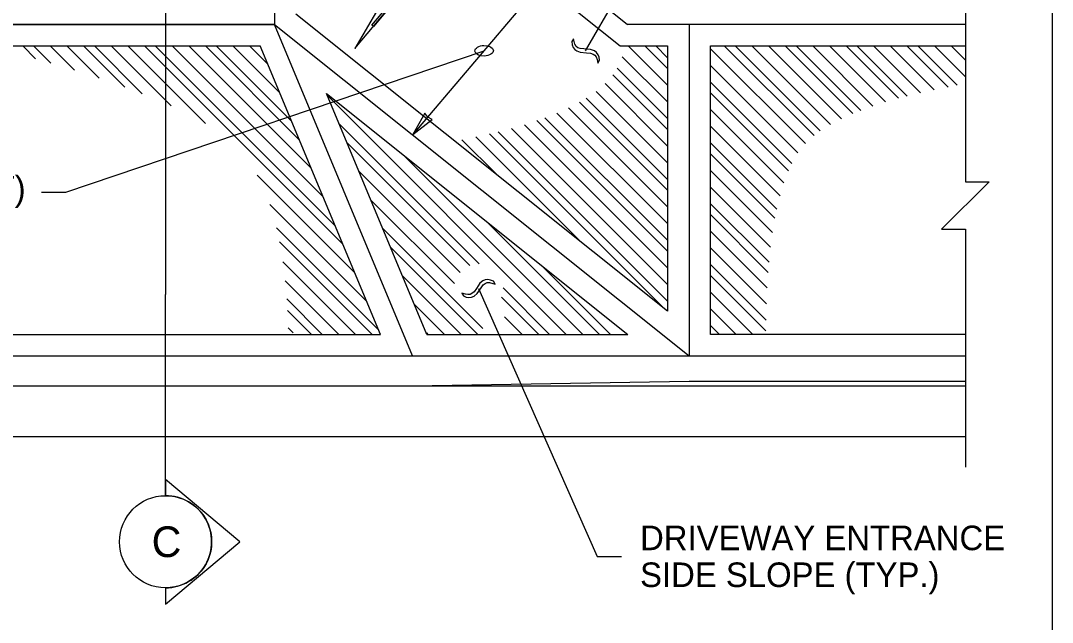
# Model space of a CAD drawing. Extents: x 99862 to 103151, y 100000 to 105076.
# Drawn here: x 102479 to 103151, y 101333 to 101725 of the extents above; entities that cross this region are included whole.
import ezdxf

# ---------------------------------------------------------------- set-up
doc = ezdxf.new("R2010")
doc.units = 0
for name, color, linetype in [('Level 1', 7, 'Continuous'), ('Level 15', 7, 'Continuous'), ('Level 20', 7, 'Continuous'), ('Level 48', 7, 'Continuous'), ('Level 50', 7, 'Continuous'), ('Level 57', 7, 'Continuous'), ('Level 58', 7, 'Continuous'), ('Level 9', 7, 'Continuous')]:
    doc.layers.add(name, color=color, linetype=linetype)

msp = doc.modelspace()

# ---------------------------------------------------------------- linework, layer by layer
at = {"layer": 'Level 1'}
msp.add_lwpolyline([(99862, 99999.5), (103151, 99999.5), (103151, 102075.5), (99862, 102075.5)], close=True, dxfattribs=at)
at = {"layer": 'Level 15'}
for p, q in [((102846.98, 101705.23), (102946.71, 101877.97)), ((102846.98, 101705.23), (102946.71, 101877.97)), ((102734.45, 101650.65), (102827.46, 101760.04)), ((102734.45, 101650.65), (102827.46, 101760.04)), ((102508.56, 101613.12), (102780.95, 101705.35)), ((102492.56, 101613.12), (102508.56, 101613.12)), ((102777.26, 101550.41), (102854.48, 101375.91)), ((102777.26, 101550.41), (102854.48, 101375.91)), ((102854.48, 101375.91), (102870.48, 101375.91)), ((102854.48, 101375.91), (102870.48, 101375.91))]:
    msp.add_line(p, q, dxfattribs=at)
for points in [[(103094.35, 101742.53), (103094.35, 101620.01), (103096.44, 101620.01)], [(103094.35, 101742.53), (103094.35, 101620.01), (103096.44, 101620.01)], [(103096.44, 101620.01), (103109.84, 101620.01), (103078.87, 101589.04), (103094.35, 101589.04), (103094.35, 101434.03)], [(103096.44, 101620.01), (103109.84, 101620.01), (103078.87, 101589.04), (103094.35, 101589.04), (103094.35, 101434.03)]]:
    msp.add_lwpolyline(points, dxfattribs=at)
msp.add_lwpolyline([(102734.45, 101650.66), (102746.98, 101660.64), (102744.16, 101662.08), (102742.28, 101664.63)], close=True, dxfattribs=at)
msp.add_lwpolyline([(102734.45, 101650.66), (102746.98, 101660.64), (102744.16, 101662.08), (102742.28, 101664.63)], close=True, dxfattribs=at)
msp.add_ellipse((102780.95, 101705.35), major_axis=(-6, -0.22), ratio=0.57735, dxfattribs=at)
at = {"layer": 'Level 20'}
for p, q in [((102573.44, 101794.07), (102573.44, 101717.31)), ((102573.44, 101717.31), (102573.44, 101546.41)), ((102573.44, 101717.31), (102573.44, 101546.41)), ((102839.03, 101713.11), (102837.97, 101711.28)), ((102839.03, 101713.11), (102837.97, 101711.28)), ((102837.97, 101711.28), (102838.33, 101709.17)), ((102837.97, 101711.28), (102838.33, 101709.17)), ((102838.33, 101709.17), (102838.98, 101707.51)), ((102838.33, 101709.17), (102838.98, 101707.51)), ((102838.98, 101707.51), (102839.93, 101706.21)), ((102838.98, 101707.51), (102839.93, 101706.21)), ((102840.01, 101709.55), (102839.03, 101713.12)), ((102840.01, 101709.55), (102839.03, 101713.12)), ((102840.88, 101708.16), (102840.01, 101709.55)), ((102840.88, 101708.16), (102840.01, 101709.55)), ((102841.97, 101707.24), (102840.88, 101708.16)), ((102841.97, 101707.24), (102840.88, 101708.16)), ((102843.37, 101706.71), (102841.97, 101707.24)), ((102843.37, 101706.71), (102841.97, 101707.24)), ((102839.93, 101706.21), (102841.26, 101705.2)), ((102839.93, 101706.21), (102841.26, 101705.2)), ((102841.26, 101705.2), (102843.56, 101704.31)), ((102841.26, 101705.2), (102843.56, 101704.31)), ((102845.79, 101706.5), (102843.37, 101706.71)), ((102845.79, 101706.5), (102843.37, 101706.71)), ((102843.56, 101704.31), (102847.64, 101704.05)), ((102843.56, 101704.31), (102847.64, 101704.05)), ((102850.18, 101706.13), (102845.79, 101706.5)), ((102850.18, 101706.13), (102845.79, 101706.5)), ((102847.64, 101704.05), (102850.18, 101703.82)), ((102847.64, 101704.05), (102850.18, 101703.82)), ((102852.74, 101705.2), (102850.18, 101706.13)), ((102852.74, 101705.2), (102850.18, 101706.13)), ((102850.18, 101703.82), (102851.99, 101703.19)), ((102850.18, 101703.82), (102851.99, 101703.19)), ((102851.99, 101703.19), (102853.04, 101702.37)), ((102851.99, 101703.19), (102853.04, 101702.37)), ((102854.14, 101704.13), (102852.74, 101705.2)), ((102854.14, 101704.13), (102852.74, 101705.2)), ((102853.04, 101702.37), (102853.85, 101701.27)), ((102853.04, 101702.37), (102853.85, 101701.27)), ((102853.85, 101701.27), (102854.47, 101699.65)), ((102853.85, 101701.27), (102854.47, 101699.65)), ((102855.15, 101702.76), (102854.14, 101704.13)), ((102855.15, 101702.76), (102854.14, 101704.13)), ((102855.79, 101701.08), (102855.15, 101702.76)), ((102855.79, 101701.08), (102855.15, 101702.76)), ((102856.04, 101699.11), (102855.79, 101701.08)), ((102856.04, 101699.11), (102855.79, 101701.08)), ((102854.47, 101699.65), (102854.99, 101697.28)), ((102854.47, 101699.65), (102854.99, 101697.28)), ((102854.99, 101697.28), (102856.04, 101699.11)), ((102854.99, 101697.28), (102856.04, 101699.11)), ((102778.17, 101553.83), (102775.9, 101550.43)), ((102778.17, 101553.83), (102775.9, 101550.43)), ((102780.09, 101555.38), (102778.17, 101553.83)), ((102780.09, 101555.38), (102778.17, 101553.83)), ((102778.95, 101550.81), (102780.34, 101552.8)), ((102778.95, 101550.81), (102780.34, 101552.8)), ((102781.63, 101556.02), (102780.09, 101555.38)), ((102781.63, 101556.02), (102780.09, 101555.38)), ((102780.34, 101552.8), (102781.5, 101553.75)), ((102780.34, 101552.8), (102781.5, 101553.75)), ((102781.5, 101553.75), (102782.84, 101554.23)), ((102781.5, 101553.75), (102782.84, 101554.23)), ((102783.23, 101556.2), (102781.63, 101556.02)), ((102783.23, 101556.2), (102781.63, 101556.02)), ((102782.84, 101554.23), (102784.48, 101554.28)), ((102782.84, 101554.23), (102784.48, 101554.28)), ((102784.99, 101555.93), (102783.23, 101556.2)), ((102784.99, 101555.93), (102783.23, 101556.2)), ((102784.48, 101554.28), (102788.06, 101553.35)), ((102784.48, 101554.28), (102788.06, 101553.35)), ((102787, 101555.18), (102784.99, 101555.93)), ((102787, 101555.18), (102784.99, 101555.93)), ((102788.06, 101553.35), (102787, 101555.19)), ((102788.06, 101553.35), (102787, 101555.19)), ((102573.44, 101442.03), (102573.44, 101546.41)), ((102768.68, 101546.71), (102766.37, 101547.45)), ((102766.37, 101547.45), (102767.42, 101545.62)), ((102768.68, 101546.71), (102766.37, 101547.45)), ((102766.37, 101547.45), (102767.42, 101545.62)), ((102770.39, 101546.44), (102768.68, 101546.71)), ((102770.39, 101546.44), (102768.68, 101546.71)), ((102771.74, 101546.59), (102770.39, 101546.44)), ((102771.74, 101546.59), (102770.39, 101546.44)), ((102772.98, 101547.09), (102771.74, 101546.59)), ((102772.98, 101547.09), (102771.74, 101546.59)), ((102774.43, 101548.34), (102772.98, 101547.09)), ((102774.43, 101548.34), (102772.98, 101547.09)), ((102774.35, 101545.44), (102776.43, 101547.19)), ((102774.35, 101545.44), (102776.43, 101547.19)), ((102775.9, 101550.43), (102774.43, 101548.34)), ((102775.9, 101550.43), (102774.43, 101548.34)), ((102776.43, 101547.19), (102778.95, 101550.81)), ((102776.43, 101547.19), (102778.95, 101550.81)), ((102767.42, 101545.62), (102769.26, 101544.86)), ((102767.42, 101545.62), (102769.26, 101544.86)), ((102769.26, 101544.86), (102771.03, 101544.57)), ((102769.26, 101544.86), (102771.03, 101544.57)), ((102771.03, 101544.57), (102772.72, 101544.76)), ((102771.03, 101544.57), (102772.72, 101544.76)), ((102772.72, 101544.76), (102774.35, 101545.44)), ((102772.72, 101544.76), (102774.35, 101545.44))]:
    msp.add_line(p, q, dxfattribs=at)
for points in [[(102707.84, 101721.96), (102738.33, 101758.37), (102730.96, 101759.66), (102764.97, 101788.24), (102708.79, 101721.16)], [(102752.03, 101774.7), (102721.54, 101738.29), (102718.97, 101745.32), (102696.8, 101706.82), (102752.98, 101773.9)]]:
    msp.add_lwpolyline(points, close=True, dxfattribs=at)
at = {"layer": 'Level 48'}
for p, q in [((102758.72, 101797.11), (102869.44, 101708.53)), ((102900.35, 101535.66), (102658.36, 101729.25)), ((102392.35, 101708.53), (102635.02, 101708.53)), ((102392.35, 101708.53), (102635.02, 101708.53)), ((102713.35, 101520.53), (102635.02, 101708.53)), ((102713.35, 101520.53), (102635.02, 101708.53)), ((102869.44, 101708.53), (102900.35, 101708.53)), ((102900.35, 101708.53), (102900.35, 101535.66)), ((102928.36, 101520.53), (102928.36, 101708.53)), ((102928.36, 101708.53), (103094.35, 101708.53)), ((102928.36, 101520.53), (102928.36, 101708.53)), ((102928.36, 101708.53), (103094.35, 101708.53)), ((102743.69, 101520.53), (102678.31, 101677.43)), ((102678.31, 101677.43), (102874.44, 101520.53)), ((102743.69, 101520.53), (102678.31, 101677.43)), ((102678.31, 101677.43), (102874.44, 101520.53)), ((102393.36, 101520.53), (102713.35, 101520.53)), ((102393.36, 101520.53), (102713.35, 101520.53)), ((102743.69, 101520.53), (102874.44, 101520.53)), ((102743.69, 101520.53), (102874.44, 101520.53)), ((103094.35, 101520.53), (102928.36, 101520.53)), ((103094.35, 101520.53), (102928.36, 101520.53))]:
    msp.add_line(p, q, dxfattribs=at)
at = {"layer": 'Level 50'}
for p, q in [((102480.39, 101708.53), (102488.77, 101700.15)), ((102480.39, 101708.53), (102488.77, 101700.15)), ((102487.46, 101708.53), (102498.68, 101697.3)), ((102487.46, 101708.53), (102498.68, 101697.3)), ((102498.32, 101708.53), (102514.22, 101692.63)), ((102498.32, 101708.53), (102514.22, 101692.63)), ((102509.18, 101708.53), (102530.24, 101687.47)), ((102509.18, 101708.53), (102530.24, 101687.47)), ((102520.04, 101708.53), (102546.91, 101681.65)), ((102520.04, 101708.53), (102546.91, 101681.65)), ((102527.11, 101708.53), (102558.29, 101677.35)), ((102527.11, 101708.53), (102558.29, 101677.35)), ((102537.97, 101708.53), (102577.06, 101669.45)), ((102537.97, 101708.53), (102577.06, 101669.45)), ((102548.84, 101708.53), (102599.5, 101657.86)), ((102548.84, 101708.53), (102599.5, 101657.86)), ((102559.7, 101708.53), (102688.82, 101579.4)), ((102559.7, 101708.53), (102688.82, 101579.4)), ((102566.77, 101708.53), (102683.77, 101591.52)), ((102566.77, 101708.53), (102683.77, 101591.52)), ((102577.63, 101708.53), (102676.01, 101610.14)), ((102577.63, 101708.53), (102676.01, 101610.14)), ((102588.49, 101708.53), (102668.25, 101628.76)), ((102588.49, 101708.53), (102668.25, 101628.76)), ((102599.35, 101708.53), (102660.5, 101647.38)), ((102599.35, 101708.53), (102660.5, 101647.38)), ((102606.42, 101708.53), (102655.45, 101659.5)), ((102606.42, 101708.53), (102655.45, 101659.5)), ((102617.28, 101708.53), (102647.69, 101678.12)), ((102617.28, 101708.53), (102647.69, 101678.12)), ((102628.14, 101708.53), (102639.93, 101696.74)), ((102628.14, 101708.53), (102639.93, 101696.74)), ((102874.71, 101708.53), (102900.35, 101682.88)), ((102874.71, 101708.53), (102900.35, 101682.88)), ((102885.57, 101708.53), (102900.35, 101693.74)), ((102885.57, 101708.53), (102900.35, 101693.74)), ((102892.64, 101708.53), (102900.35, 101700.81)), ((102892.64, 101708.53), (102900.35, 101700.81)), ((102937.34, 101708.53), (102995.8, 101650.07)), ((102937.34, 101708.53), (102995.8, 101650.07)), ((102944.41, 101708.53), (102999.85, 101653.09)), ((102944.41, 101708.53), (102999.85, 101653.09)), ((102955.27, 101708.53), (103006.51, 101657.29)), ((102955.27, 101708.53), (103006.51, 101657.29)), ((102966.13, 101708.53), (103013.62, 101661.04)), ((102966.13, 101708.53), (103013.62, 101661.04)), ((102976.99, 101708.53), (103021.11, 101664.41)), ((102976.99, 101708.53), (103021.11, 101664.41)), ((102984.06, 101708.53), (103026.15, 101666.44)), ((102984.06, 101708.53), (103026.15, 101666.44)), ((102994.93, 101708.53), (103034.13, 101669.33)), ((102994.93, 101708.53), (103034.13, 101669.33)), ((103005.79, 101708.53), (103042.35, 101671.96)), ((103005.79, 101708.53), (103042.35, 101671.96)), ((103016.65, 101708.53), (103050.79, 101674.38)), ((103016.65, 101708.53), (103050.79, 101674.38)), ((103023.72, 101708.53), (103056.4, 101675.85)), ((103023.72, 101708.53), (103056.4, 101675.85)), ((103034.58, 101708.53), (103065.15, 101677.96)), ((103034.58, 101708.53), (103065.15, 101677.96)), ((103045.44, 101708.53), (103074.06, 101679.91)), ((103045.44, 101708.53), (103074.06, 101679.91)), ((103056.3, 101708.53), (103083.12, 101681.71)), ((103056.3, 101708.53), (103083.12, 101681.71)), ((103063.37, 101708.53), (103089.09, 101682.81)), ((103063.37, 101708.53), (103089.09, 101682.81)), ((103074.23, 101708.53), (103094.35, 101688.41)), ((103074.23, 101708.53), (103094.35, 101688.41)), ((103085.1, 101708.53), (103094.35, 101699.27)), ((103085.1, 101708.53), (103094.35, 101699.27)), ((102870.92, 101701.45), (102900.35, 101672.02)), ((102870.92, 101701.45), (102900.35, 101672.02)), ((102928.36, 101706.64), (102990.13, 101644.87)), ((102928.36, 101706.64), (102990.13, 101644.87)), ((102867.62, 101693.89), (102900.35, 101661.16)), ((102867.62, 101693.89), (102900.35, 101661.16)), ((102928.36, 101695.78), (102985.33, 101638.81)), ((102928.36, 101695.78), (102985.33, 101638.81)), ((102864.79, 101689.65), (102900.35, 101654.09)), ((102864.79, 101689.65), (102900.35, 101654.09)), ((102859.68, 101683.9), (102900.35, 101643.23)), ((102859.68, 101683.9), (102900.35, 101643.23)), ((102928.36, 101684.92), (102981.35, 101631.93)), ((102928.36, 101684.92), (102981.35, 101631.93)), ((102678.36, 101677.3), (102678.36, 101677.39)), ((102678.36, 101677.3), (102678.36, 101677.39)), ((102678.88, 101676.07), (102834.42, 101520.53)), ((102678.88, 101676.07), (102834.42, 101520.53)), ((102847.42, 101674.43), (102900.35, 101621.5)), ((102847.42, 101674.43), (102900.35, 101621.5)), ((102853.84, 101678.88), (102900.35, 101632.36)), ((102853.84, 101678.88), (102900.35, 101632.36)), ((102928.36, 101677.85), (102979.11, 101627.1)), ((102928.36, 101677.85), (102979.11, 101627.1)), ((102835.85, 101668.08), (102900.35, 101603.57)), ((102835.85, 101668.08), (102900.35, 101603.57)), ((102842.99, 101671.79), (102900.35, 101614.43)), ((102842.99, 101671.79), (102900.35, 101614.43)), ((102928.36, 101666.99), (102976.13, 101619.22)), ((102928.36, 101666.99), (102976.13, 101619.22)), ((102820.55, 101661.65), (102900.35, 101581.85)), ((102820.55, 101661.65), (102900.35, 101581.85)), ((102828.35, 101664.71), (102900.35, 101592.71)), ((102828.35, 101664.71), (102900.35, 101592.71)), ((102686.63, 101657.45), (102777.68, 101566.4)), ((102686.63, 101657.45), (102777.68, 101566.4)), ((102798.7, 101654.71), (102900.35, 101553.06)), ((102798.7, 101654.71), (102900.35, 101553.06)), ((102807.12, 101657.15), (102900.35, 101563.92)), ((102807.12, 101657.15), (102900.35, 101563.92)), ((102815.34, 101659.79), (102900.35, 101574.78)), ((102815.34, 101659.79), (102900.35, 101574.78)), ((102928.36, 101656.13), (102973.62, 101610.87)), ((102928.36, 101656.13), (102973.62, 101610.87)), ((102766.43, 101647.32), (102789.08, 101624.68)), ((102766.43, 101647.32), (102789.08, 101624.68)), ((102775.48, 101649.14), (102843.38, 101581.23)), ((102775.48, 101649.14), (102843.38, 101581.23)), ((102784.37, 101651.1), (102897.69, 101537.79)), ((102784.37, 101651.1), (102897.69, 101537.79)), ((102790.08, 101652.47), (102900.35, 101542.19)), ((102790.08, 101652.47), (102900.35, 101542.19)), ((102691.68, 101645.33), (102771.63, 101565.39)), ((102691.68, 101645.33), (102771.63, 101565.39)), ((102928.36, 101645.27), (102971.51, 101602.11)), ((102928.36, 101645.27), (102971.51, 101602.11)), ((102728.64, 101637.17), (102845.28, 101520.53)), ((102728.64, 101637.17), (102845.28, 101520.53)), ((102928.36, 101638.19), (102970.33, 101596.22)), ((102928.36, 101638.19), (102970.33, 101596.22)), ((102699.44, 101626.71), (102765.21, 101560.94)), ((102699.44, 101626.71), (102765.21, 101560.94)), ((102928.36, 101627.33), (102968.78, 101586.92)), ((102928.36, 101627.33), (102968.78, 101586.92)), ((102633.07, 101624.29), (102696.58, 101560.78)), ((102633.07, 101624.29), (102696.58, 101560.78)), ((102928.36, 101616.47), (102967.51, 101577.33)), ((102928.36, 101616.47), (102967.51, 101577.33)), ((102707.2, 101608.09), (102761.6, 101553.69)), ((102707.2, 101608.09), (102761.6, 101553.69)), ((102641.33, 101605.17), (102704.34, 101542.16)), ((102641.33, 101605.17), (102704.34, 101542.16)), ((102928.36, 101605.61), (102966.49, 101567.49)), ((102928.36, 101605.61), (102966.49, 101567.49)), ((102782.94, 101593.73), (102856.14, 101520.53)), ((102782.94, 101593.73), (102856.14, 101520.53)), ((102928.36, 101598.54), (102965.95, 101560.96)), ((102928.36, 101598.54), (102965.95, 101560.96)), ((102645.73, 101589.91), (102712.09, 101523.55)), ((102645.73, 101589.91), (102712.09, 101523.55)), ((102714.96, 101589.47), (102780.01, 101524.42)), ((102714.96, 101589.47), (102780.01, 101524.42)), ((102928.36, 101587.68), (102965.29, 101550.76)), ((102928.36, 101587.68), (102965.29, 101550.76)), ((102647.69, 101580.87), (102708.04, 101520.53)), ((102647.69, 101580.87), (102708.04, 101520.53)), ((102720.01, 101577.35), (102776.83, 101520.53)), ((102720.01, 101577.35), (102776.83, 101520.53)), ((102928.36, 101576.82), (102964.82, 101540.36)), ((102928.36, 101576.82), (102964.82, 101540.36)), ((102649.89, 101567.82), (102697.18, 101520.53)), ((102649.89, 101567.82), (102697.18, 101520.53)), ((102818.3, 101565.44), (102863.21, 101520.53)), ((102818.3, 101565.44), (102863.21, 101520.53)), ((102928.36, 101565.96), (102964.52, 101529.8)), ((102928.36, 101565.96), (102964.52, 101529.8)), ((102651.38, 101555.47), (102686.32, 101520.53)), ((102651.38, 101555.47), (102686.32, 101520.53)), ((102727.77, 101558.73), (102765.97, 101520.53)), ((102727.77, 101558.73), (102765.97, 101520.53)), ((102928.36, 101558.89), (102964.42, 101522.83)), ((102928.36, 101558.89), (102964.42, 101522.83)), ((102793.25, 101550.83), (102823.56, 101520.53)), ((102793.25, 101550.83), (102823.56, 101520.53)), ((102928.36, 101548.02), (102955.86, 101520.53)), ((102928.36, 101548.02), (102955.86, 101520.53)), ((102652.37, 101543.61), (102675.46, 101520.53)), ((102652.37, 101543.61), (102675.46, 101520.53)), ((102735.53, 101540.11), (102755.11, 101520.53)), ((102735.53, 101540.11), (102755.11, 101520.53)), ((102792.23, 101544.78), (102816.49, 101520.53)), ((102792.23, 101544.78), (102816.49, 101520.53)), ((102652.81, 101536.11), (102668.39, 101520.53)), ((102652.81, 101536.11), (102668.39, 101520.53)), ((102928.36, 101537.16), (102945, 101520.53)), ((102928.36, 101537.16), (102945, 101520.53)), ((102794.15, 101532), (102805.63, 101520.53)), ((102794.15, 101532), (102805.63, 101520.53)), ((102928.36, 101526.3), (102934.14, 101520.53)), ((102928.36, 101526.3), (102934.14, 101520.53)), ((102653.21, 101524.84), (102656.58, 101521.47)), ((102653.21, 101524.84), (102656.58, 101521.47)), ((102743.28, 101521.49), (102744.25, 101520.53)), ((102743.28, 101521.49), (102744.25, 101520.53)), ((102872.6, 101522), (102874.07, 101520.53)), ((102872.6, 101522), (102874.07, 101520.53))]:
    msp.add_line(p, q, dxfattribs=at)
at = {"layer": 'Level 57'}
for p, q in [((102694.34, 101866.54), (102874.35, 101722.53)), ((102694.34, 101866.54), (102874.35, 101722.53)), ((102644.35, 101722.53), (102914.35, 101506.53)), ((102644.35, 101722.53), (102914.35, 101506.53)), ((103094.35, 101722.53), (102874.35, 101722.53)), ((103094.35, 101722.53), (102874.35, 101722.53)), ((102392.35, 101506.53), (102734.35, 101506.53)), ((102392.35, 101506.53), (102734.35, 101506.53)), ((102914.35, 101506.53), (103094.35, 101506.53)), ((102914.35, 101506.53), (103094.35, 101506.53)), ((102392.35, 101487.03), (102734.35, 101487.03)), ((102392.35, 101487.03), (102734.35, 101487.03)), ((102734.35, 101487.03), (102914.35, 101490.03)), ((102734.35, 101487.03), (102914.35, 101490.03)), ((102734.35, 101487.03), (102914.35, 101487.03)), ((102734.35, 101487.03), (102914.35, 101487.03)), ((102914.35, 101490.03), (103094.35, 101490.03)), ((102914.35, 101490.03), (103094.35, 101490.03)), ((102914.35, 101487.03), (103094.35, 101487.03)), ((102914.35, 101487.03), (103094.35, 101487.03)), ((102392.35, 101454.03), (102734.35, 101454.03)), ((102392.35, 101454.03), (102734.35, 101454.03)), ((102734.35, 101454.03), (102914.35, 101454.03)), ((102734.35, 101454.03), (102914.35, 101454.03)), ((102914.35, 101454.03), (103094.35, 101454.03)), ((102914.35, 101454.03), (103094.35, 101454.03))]:
    msp.add_line(p, q, dxfattribs=at)
msp.add_lwpolyline([(102734.35, 101506.53), (102914.35, 101506.53)], dxfattribs=at)
msp.add_lwpolyline([(102734.35, 101506.53), (102914.35, 101506.53)], dxfattribs=at)
at = {"layer": 'Level 58'}
for p, q in [((102644.35, 101866.53), (102644.35, 101722.53)), ((102644.35, 101866.53), (102644.35, 101722.53)), ((102644.31, 101722.53), (102392.35, 101722.53)), ((102644.31, 101722.53), (102392.35, 101722.53)), ((102914.35, 101722.55), (102914.35, 101506.53)), ((102914.35, 101722.55), (102914.35, 101506.53))]:
    msp.add_line(p, q, dxfattribs=at)
for points in [[(102392.35, 101722.53), (102644.35, 101722.53)], [(102392.35, 101722.53), (102644.35, 101722.53)], [(102734.35, 101506.53), (102644.35, 101722.53)], [(102734.35, 101506.53), (102644.35, 101722.53)]]:
    msp.add_lwpolyline(points, dxfattribs=at)
at = {"layer": 'Level 9'}
for p, q in [((102573.44, 101415.43), (102573.44, 101442.03)), ((102573.44, 101426.03), (102573.44, 101415.43)), ((102621.9, 101385.43), (102573.44, 101426.03)), ((102573.44, 101344.83), (102621.9, 101385.43)), ((102573.44, 101355.43), (102573.44, 101344.83))]:
    msp.add_line(p, q, dxfattribs=at)
msp.add_circle((102573.44, 101385.43), 30, dxfattribs=at)
msp.add_arc((102573.44, 101385.43), 30, 269.99779, 90.00221, dxfattribs=at)

# ---------------------------------------------------------------- texts
at = {"layer": 'Level 20'}
for s, height, p in [('(SEE CONTRACT)', 16, (102300.45, 101607.74)), ('C', 20, (102564.39, 101375.43)), ('DRIVEWAY ENTRANCE', 16, (102882.48, 101379.92)), ('SIDE SLOPE (TYP.)', 16, (102882.48, 101355.92))]:
    msp.add_text(s, height=height, dxfattribs=at).set_placement(p)

doc.saveas('drawing.dxf')
